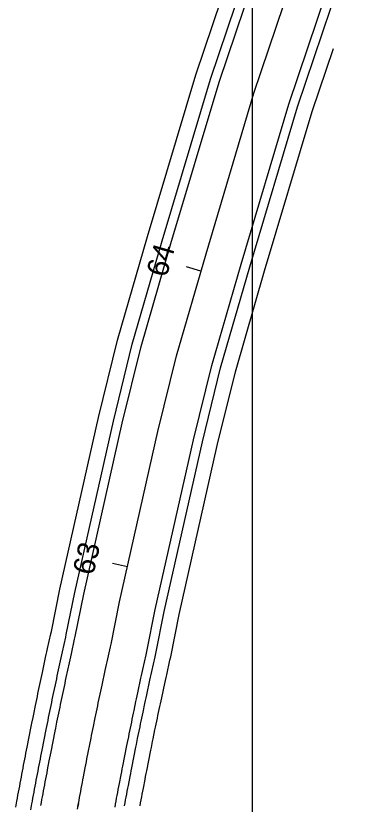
# Model space of a CAD drawing. Extents: x 2318076 to 2324211, y 613525 to 630327.
# Drawn here: x 2318619 to 2318733.3, y 621113.3 to 621372 of the extents above; entities that cross this region are included whole.
import ezdxf

# ---------------------------------------------------------------- set-up
doc = ezdxf.new("R2010")
doc.units = 0
for name, color, linetype in [('GE_P_CL_50', 7, 'Continuous'), ('PV_P_EOP', 7, 'Continuous'), ('PV_P_Shoulder', 7, 'Continuous'), ('RD_X_GR_Lt', 7, 'Continuous'), ('RD_X_GR_Rt', 7, 'Continuous'), ('SC_Scratch3', 7, 'Continuous')]:
    doc.layers.add(name, color=color, linetype=linetype)

msp = doc.modelspace()

# ---------------------------------------------------------------- linework, layer by layer
at = {"layer": 'GE_P_CL_50'}
for p, q in [((2318679.71, 621288.18), (2318674.91, 621289.57)), ((2318655.58, 621191.17), (2318650.7, 621192.27))]:
    msp.add_line(p, q, dxfattribs=at)
for points in [[(2318639.17, 621111.67), (2318639.53, 621113.61), (2318639.71, 621114.59), (2318639.89, 621115.56), (2318640.08, 621116.53), (2318640.26, 621117.5), (2318640.44, 621118.47), (2318640.63, 621119.44), (2318640.81, 621120.41), (2318641, 621121.38), (2318641.18, 621122.35), (2318641.74, 621125.26), (2318641.93, 621126.23), (2318642.12, 621127.2), (2318642.31, 621128.17), (2318643.66, 621134.95), (2318643.85, 621135.92), (2318644.24, 621137.85), (2318644.44, 621138.82), (2318645.03, 621141.72), (2318645.23, 621142.69), (2318645.43, 621143.66), (2318645.63, 621144.63), (2318645.83, 621145.59), (2318646.03, 621146.56), (2318646.64, 621149.46), (2318646.85, 621150.43), (2318647.05, 621151.39), (2318647.26, 621152.36), (2318648.29, 621157.19), (2318648.5, 621158.15), (2318648.71, 621159.12), (2318648.92, 621160.08), (2318649.99, 621164.91), (2318650.2, 621165.87), (2318652.99, 621179.7), (2318665.59, 621235.58), (2318671.65, 621260.37), (2318681.36, 621293.88), (2318697.08, 621346.57), (2318719.13, 621411.93)], [(2318639.35, 621112.64), (2318639.53, 621113.61), (2318639.35, 621112.64)]]:
    msp.add_lwpolyline(points, dxfattribs=at)
at = {"layer": 'PV_P_EOP'}
for points in [[(2318627.19, 621112.87), (2318627.37, 621113.85), (2318627.55, 621114.83), (2318627.73, 621115.81), (2318627.92, 621116.79), (2318628.1, 621117.76), (2318628.28, 621118.74), (2318628.47, 621119.72), (2318628.65, 621120.7), (2318628.84, 621121.68), (2318629.02, 621122.66), (2318629.21, 621123.63), (2318629.4, 621124.62), (2318629.96, 621127.54), (2318630.15, 621128.52), (2318630.34, 621129.5), (2318630.54, 621130.49), (2318631.89, 621137.3), (2318632.09, 621138.29), (2318632.48, 621140.24), (2318632.68, 621141.22), (2318633.28, 621144.14), (2318633.48, 621145.12), (2318633.68, 621146.09), (2318633.88, 621147.07), (2318634.08, 621148.04), (2318634.29, 621149.02), (2318634.9, 621151.93), (2318635.11, 621152.91), (2318635.31, 621153.89), (2318635.52, 621154.87), (2318636.56, 621159.72), (2318636.78, 621160.7), (2318636.99, 621161.67), (2318637.2, 621162.65), (2318638.27, 621167.5), (2318638.46, 621168.36), (2318641.25, 621182.21), (2318653.91, 621238.32), (2318660.05, 621263.47), (2318669.85, 621297.27), (2318685.64, 621350.2), (2318707.83, 621415.98)], [(2318651.51, 621112.38), (2318651.69, 621113.35), (2318651.87, 621114.31), (2318652.05, 621115.27), (2318652.23, 621116.24), (2318652.41, 621117.2), (2318652.6, 621118.16), (2318652.78, 621119.12), (2318652.97, 621120.08), (2318653.52, 621122.98), (2318653.71, 621123.94), (2318653.9, 621124.9), (2318654.08, 621125.85), (2318655.42, 621132.6), (2318655.61, 621133.55), (2318656, 621135.47), (2318656.2, 621136.42), (2318656.79, 621139.31), (2318656.98, 621140.27), (2318657.18, 621141.23), (2318657.38, 621142.19), (2318657.58, 621143.15), (2318657.78, 621144.1), (2318658.39, 621146.99), (2318658.59, 621147.94), (2318658.79, 621148.9), (2318658.99, 621149.85), (2318660.02, 621154.66), (2318660.23, 621155.61), (2318660.44, 621156.56), (2318660.65, 621157.51), (2318661.7, 621162.31), (2318661.94, 621163.38), (2318664.73, 621177.19), (2318677.27, 621232.84), (2318683.25, 621257.27), (2318692.87, 621290.49), (2318708.52, 621342.94), (2318730.43, 621407.88)]]:
    msp.add_lwpolyline(points, dxfattribs=at)
at = {"layer": 'PV_P_Shoulder'}
for points in [[(2318623.88, 621111.45), (2318624.24, 621113.41), (2318624.42, 621114.39), (2318624.6, 621115.37), (2318624.78, 621116.36), (2318624.97, 621117.34), (2318625.15, 621118.32), (2318625.33, 621119.3), (2318625.52, 621120.28), (2318625.7, 621121.26), (2318625.89, 621122.24), (2318626.08, 621123.22), (2318626.26, 621124.2), (2318626.45, 621125.18), (2318627.02, 621128.11), (2318627.21, 621129.09), (2318627.4, 621130.07), (2318627.59, 621131.07), (2318628.95, 621137.89), (2318629.15, 621138.88), (2318629.54, 621140.83), (2318629.74, 621141.82), (2318630.34, 621144.74), (2318630.54, 621145.72), (2318630.74, 621146.7), (2318630.94, 621147.67), (2318631.15, 621148.65), (2318631.35, 621149.63), (2318631.96, 621152.55), (2318632.17, 621153.53), (2318632.38, 621154.51), (2318632.59, 621155.49), (2318633.63, 621160.35), (2318633.84, 621161.34), (2318634.06, 621162.31), (2318634.27, 621163.29), (2318635.34, 621168.15), (2318635.53, 621168.98), (2318638.32, 621182.83), (2318650.99, 621239.01), (2318657.15, 621264.24), (2318666.97, 621298.11), (2318682.78, 621351.11), (2318705.01, 621416.99)], [(2318654.64, 621112.8), (2318654.82, 621113.76), (2318655, 621114.72), (2318655.18, 621115.68), (2318655.36, 621116.64), (2318655.54, 621117.6), (2318655.73, 621118.56), (2318655.91, 621119.52), (2318656.47, 621122.41), (2318656.65, 621123.36), (2318656.84, 621124.32), (2318657.03, 621125.27), (2318658.36, 621132.01), (2318658.55, 621132.95), (2318658.94, 621134.87), (2318659.14, 621135.83), (2318659.73, 621138.71), (2318659.92, 621139.66), (2318660.12, 621140.62), (2318660.32, 621141.58), (2318660.52, 621142.54), (2318660.72, 621143.49), (2318661.32, 621146.37), (2318661.52, 621147.32), (2318661.72, 621148.28), (2318661.93, 621149.22), (2318662.96, 621154.02), (2318663.16, 621154.97), (2318663.37, 621155.93), (2318663.58, 621156.87), (2318664.63, 621161.67), (2318664.87, 621162.76), (2318667.66, 621176.57), (2318680.19, 621232.15), (2318686.15, 621256.5), (2318695.75, 621289.65), (2318711.38, 621342.03), (2318733.25, 621406.87)]]:
    msp.add_lwpolyline(points, dxfattribs=at)
at = {"layer": 'RD_X_GR_Lt'}
msp.add_lwpolyline([(2318618.96, 621112.35), (2318619.32, 621114.31), (2318619.5, 621115.3), (2318619.69, 621116.29), (2318619.87, 621117.27), (2318620.05, 621118.25), (2318620.24, 621119.24), (2318620.42, 621120.22), (2318620.6, 621121.2), (2318620.79, 621122.19), (2318620.98, 621123.17), (2318621.16, 621124.15), (2318621.35, 621125.14), (2318621.54, 621126.13), (2318622.11, 621129.06), (2318622.3, 621130.05), (2318622.49, 621131.03), (2318622.69, 621132.03), (2318624.04, 621138.87), (2318624.24, 621139.87), (2318624.64, 621141.83), (2318624.84, 621142.82), (2318625.44, 621145.74), (2318625.64, 621146.73), (2318625.85, 621147.71), (2318626.05, 621148.69), (2318626.25, 621149.67), (2318626.46, 621150.66), (2318627.07, 621153.58), (2318627.28, 621154.57), (2318627.49, 621155.55), (2318627.7, 621156.54), (2318628.74, 621161.41), (2318628.96, 621162.4), (2318629.17, 621163.37), (2318629.39, 621164.36), (2318630.46, 621169.23), (2318630.63, 621170.02), (2318633.43, 621183.88), (2318646.12, 621240.15), (2318652.32, 621265.53), (2318662.17, 621299.52), (2318678.02, 621352.63), (2318700.3, 621418.68)], dxfattribs=at)
at = {"layer": 'RD_X_GR_Rt'}
msp.add_lwpolyline([(2318659.73, 621112.83), (2318659.91, 621113.79), (2318660.09, 621114.75), (2318660.27, 621115.71), (2318660.46, 621116.66), (2318660.64, 621117.62), (2318660.82, 621118.57), (2318661.38, 621121.46), (2318661.56, 621122.41), (2318661.75, 621123.36), (2318661.93, 621124.3), (2318663.27, 621131.03), (2318663.46, 621131.96), (2318663.84, 621133.88), (2318664.04, 621134.83), (2318664.62, 621137.7), (2318664.82, 621138.65), (2318665.02, 621139.61), (2318665.21, 621140.56), (2318665.41, 621141.52), (2318665.61, 621142.46), (2318666.21, 621145.34), (2318666.41, 621146.29), (2318666.62, 621147.24), (2318666.82, 621148.18), (2318667.84, 621152.97), (2318668.05, 621153.91), (2318668.26, 621154.86), (2318668.46, 621155.8), (2318669.51, 621160.59), (2318669.77, 621161.72), (2318672.55, 621175.52), (2318685.06, 621231.01), (2318690.98, 621255.21), (2318700.55, 621288.24), (2318716.14, 621340.51), (2318723.13, 621361.23)], dxfattribs=at)
at = {"layer": 'SC_Scratch3'}
msp.add_line((2318696.66, 614778.41), (2318696.66, 630327.22), dxfattribs=at)

# ---------------------------------------------------------------- texts
at = {"layer": 'GE_P_CL_50'}
for s, rotation, p in [('64', 73.8403, (2318668.36, 621285.86)), ('63', 77.2933, (2318644.39, 621188.17))]:
    msp.add_text(s, height=7, rotation=rotation, dxfattribs=at).set_placement(p)

doc.saveas('drawing.dxf')
